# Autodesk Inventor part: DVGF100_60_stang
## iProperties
Created: 2010-04
Part Number: DVGF100_60_stang
Document SubType Name: Modeling
Designer: TB
Mass: 988.11 g
Surface Area: 744.287 cm^2
Volume: 988.11 cm^3
Density: 1 g/cm^3
Author: TB
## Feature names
1. Revolution1
2. Fillet1
3. Revolution2
4. Extrusion1
5. Extrusion2
6. Chamfer1
7. Chamfer2
8. Fillet2
